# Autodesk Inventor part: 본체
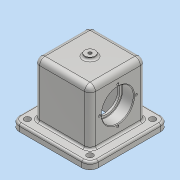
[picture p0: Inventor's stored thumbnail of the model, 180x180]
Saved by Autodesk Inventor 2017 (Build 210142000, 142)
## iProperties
Part Number: 본체
Material: 알루미늄 6061
Document SubType Name: Modeling
Designer: MRC
Density: 2.7 g/cm^3
Appearance: 알루미늄 - 평지
Mass: 1059.83 g
Surface Area: 721.846 cm^2
Volume: 392.53 cm^3
Author: MRC
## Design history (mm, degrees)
sketch "스케치1"
  geometry: L1 (-58, 58)-(58, 58); L2 (58, 58)-(58, -58); L3 (58, -58)-(-58, -58); L4 (-58, -58)-(-58, 58); L5 (-58, 58)-(58, -58); L6 (58, 58)-(-58, -58); 1 further point
  constraints: 12 end point, 2 midpoint, 2 parallel, 1 horizontal, 1 perpendicular
  dimensions: "d0" = 116 distance of L2.end L3.end; "d1" = 116 distance of L1.end L2.end
extrude "돌출1" new body sketch "스케치1" distance "d2" = 10; taper "d3" = 0 deg
sketch "스케치2"
  geometry: L1 (-41, 41)-(41, 41); L2 (41, 41)-(41, -41); L3 (41, -41)-(-41, -41); L4 (-41, -41)-(-41, 41); L5 (-41, 41)-(41, -41); L6 (41, 41)-(-41, -41); 1 further point
  constraints: 12 end point, 2 midpoint, 2 parallel, 1 horizontal, 1 perpendicular
  dimensions: "d4" = 82 distance of L2.end L3.end; "d5" = 82 distance of L1.end L2.end
extrude "돌출2" join sketch "스케치2" distance "d6" = 80; taper "d7" = 0 deg
node "작업 평면1"
sketch "스케치3"
  geometry: C1 r 7.5 at (0, 0); 1 further point
  constraints: 1 centre point, 1 coincident
  dimensions: "d9" = 15 diameter of C1
extrude "돌출3" join sketch "스케치3" stored distance "d10" = 161.25; taper "d11" = 0 deg
sketch "스케치4"
  geometry: L1 (-10, -17)-(-10, 99) reference; C1 r 23.5 at (38, 41); 2 further points
  constraints: 1 centre point, 1 horizontal alignment, 1 midpoint
  dimensions: "d12" = 47 diameter of C1; "d13" = 48 distance from line of L1 C1.centre
extrude "돌출4" cut sketch "스케치4" distance "d14" = 17; taper "d15" = 0 deg
sketch "스케치5"
  geometry: L1 (-21, 30)-(21, 30); L2 (21, 30)-(21, -30); L3 (21, -30)-(-21, -30); L4 (-21, -30)-(-21, 30); L5 (58, 58)-(-58, 58) reference; 4 further points
  constraints: 8 end point, 3 midpoint, 2 parallel, 1 horizontal, 1 horizontal alignment, 1 perpendicular, 1 vertical alignment
  dimensions: "d16" = 42 distance of L2.end L3.end; "d17" = 60 distance of L1.end L2.end
extrude "돌출5" cut sketch "스케치5" distance "d18" = 80; taper "d19" = 0 deg
sketch "스케치6"
  geometry: L1 (-48, -58)-(-48, 58) reference; C1 r 20 at (0, 0); 2 further points
  constraints: 1 centre point, 1 horizontal alignment, 1 midpoint
  dimensions: "d20" = 40 diameter of C1; "d21" = 48 distance from line of L1 C1.centre
extrude "돌출6" cut sketch "스케치6" distance "d22" = 104.5; taper "d23" = 0 deg
sketch "스케치7"
  geometry: C1 r 20 at (-38, 41) reference; C2 r 23.5 at (-38, 41); 1 further point
  constraints: 1 centre point, 1 coincident
  dimensions: "d24" = 47 diameter of C2
extrude "돌출7" cut sketch "스케치7" distance "d25" = 17; taper "d26" = 0 deg
sketch "스케치8" dims "d27" = 54
  geometry: C1 r 20 at (-38, 41) reference; 3 further points
  constraints: 2 horizontal alignment, 1 coincident, 2 other
hole "구멍1" sketch "스케치8" at (-65, 41) diameter "d28" = 3.242; stored, may be unused: countersink angle "d32" = 90 deg, drill point angle "d34" = 118 deg; dims "d29" = 8, "d30" = 4, "d31" = 2, "d33" = 10
sketch "스케치9"
  geometry: 2 further points
  constraints: 1 coincident
hole "구멍2" sketch "스케치9" at (0, 0) diameter "d38" = 4.917; stored, may be unused: countersink angle "d42" = 90 deg, drill point angle "d44" = 118 deg; dims "d39" = 38.35, "d40" = 4, "d41" = 2, "d43" = 38.35
fillet "모깎기1" dims "d45" = 12
sketch "스케치10"
  geometry: C1 r 4.5 at (-46, 46); C2 r 4.5 at (46, 46); C3 r 4.5 at (-46, -46); C4 r 4.5 at (46, -46); A1 r 12 centre (-46, 46) between (-46, 58) and (-58, 46) reference; A2 r 12 centre (46, 46) between (58, 46) and (46, 58) reference; A3 r 12 centre (-46, -46) between (-58, -46) and (-46, -58) reference; A4 r 12 centre (46, -46) between (46, -58) and (58, -46) reference; 1 further point
  constraints: 4 centre point, 4 coincident
  dimensions: "d46" = 9 diameter of C1; "d47" = 9 diameter of C2; "d48" = 9 diameter of C3; "d49" = 9 diameter of C4
extrude "돌출8" cut sketch "스케치10" distance "d50" = 17; taper "d51" = 0 deg
fillet "모깎기2" dims "d52" = 8
fillet "모깎기3" dims "d53" = 8
fillet "모깎기4" dims "d54" = 3
fillet "모깎기5" dims "d55" = 3
chamfer "모따기1" distance "d56" = 1; stored, may be unused: second distance "d57" = 2, angle "d58" = 45 deg
fillet "모깎기6" dims "d59" = 0.6
fillet "모깎기7" dims "d60" = 3
sketch "스케치11"
  geometry: L1 (-13, 82)-(79, 82) reference; 3 further points
  constraints: 1 midpoint, 1 vertical alignment, 1 other
  dimensions: "d61" = 48 distance from line of L1 point (33, 34)
feature "엠보싱1" sketch "스케치11" dims "d0" = 116, "d1" = 116, "d62" = 0.5, "d63" = 0
fillet "모깎기8" dims "d64" = 3
node "솔리드1"
pattern_circular "원형 패턴1" dims angle "d36" = 360 deg
mirror "미러1"
other parameters: "d8" = 94
